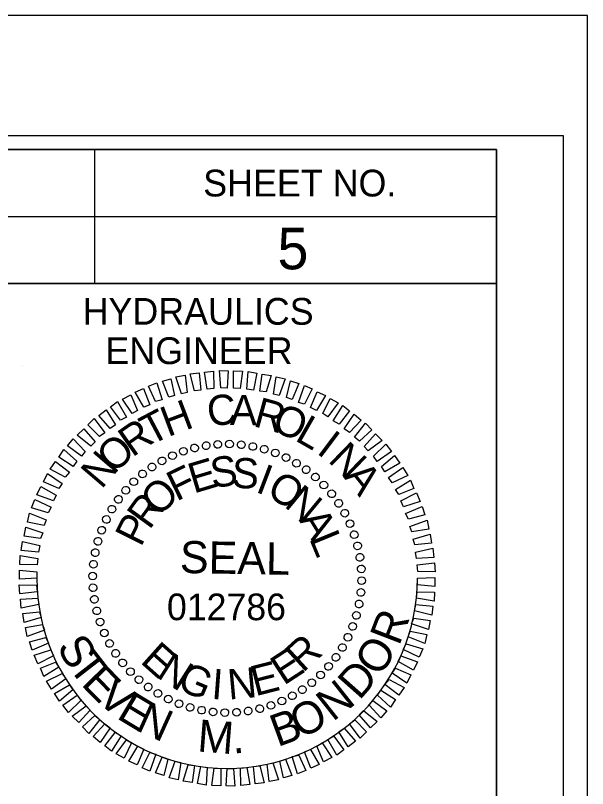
# Model space of a CAD drawing. Extents: x 10033 to 11717, y 9950 to 11050.
# Drawn here: x 11610.3 to 11717, y 10905.6 to 11050 of the extents above; entities that cross this region are included whole.
import ezdxf

# ---------------------------------------------------------------- set-up
doc = ezdxf.new("R2010")
doc.units = 0
for name, color, linetype in [('Default', 7, 'Continuous'), ('Scratch_Level_0', 7, 'Continuous'), ('Sheet Cutting Line CELL', 7, 'Continuous'), ('Sheet Data Field CELL', 7, 'Continuous'), ('Sheet PE Seal CELL', 7, 'Continuous'), ('Sheet Plot Border Inside CELL', 7, 'Continuous'), ('Sheet Plot Border Outside CELL', 7, 'Continuous'), ('Sheet Profile CELL', 7, 'Continuous')]:
    doc.layers.add(name, color=color, linetype=linetype)

msp = doc.modelspace()

# ---------------------------------------------------------------- linework, layer by layer
at = {"layer": 'Scratch_Level_0'}
msp.add_arc((11649.77, 10944.9), 35.5, 180, 360, dxfattribs=at)
at = {"layer": 'Sheet Cutting Line CELL'}
msp.add_line((11717, 11050), (10033, 11050), dxfattribs=at)
at = {"layer": 'Sheet PE Seal CELL'}
for p, q in [((11611.67, 10984.6), (11611.67, 10984.6)), ((11645.87, 10969.65), (11645.87, 10969.65)), ((11648.02, 10969.95), (11648.02, 10969.95)), ((11650.22, 10970), (11650.22, 10970)), ((11652.42, 10969.85), (11652.42, 10969.85)), ((11654.57, 10969.5), (11654.57, 10969.5)), ((11641.57, 10968.65), (11641.57, 10968.65)), ((11643.67, 10969.25), (11643.67, 10969.25)), ((11656.67, 10969.05), (11656.67, 10969.05)), ((11658.77, 10968.35), (11658.77, 10968.35)), ((11637.62, 10966.85), (11637.62, 10966.85)), ((11639.57, 10967.85), (11639.57, 10967.85)), ((11660.77, 10967.45), (11660.77, 10967.45)), ((11635.72, 10965.7), (11635.72, 10965.7)), ((11662.72, 10966.45), (11662.72, 10966.45)), ((11664.52, 10965.2), (11664.52, 10965.2)), ((11633.97, 10964.45), (11633.97, 10964.45)), ((11666.27, 10963.85), (11666.27, 10963.85)), ((11632.32, 10962.95), (11632.32, 10962.95)), ((11667.82, 10962.35), (11667.82, 10962.35)), ((11630.82, 10961.4), (11630.82, 10961.4)), ((11629.47, 10959.65), (11629.47, 10959.65)), ((11669.32, 10960.7), (11669.32, 10960.7)), ((11670.57, 10958.95), (11670.57, 10958.95)), ((11628.22, 10957.85), (11628.22, 10957.85)), ((11671.72, 10957.05), (11671.72, 10957.05)), ((11627.22, 10955.9), (11627.22, 10955.9)), ((11672.72, 10955.1), (11672.72, 10955.1)), ((11626.32, 10953.9), (11626.32, 10953.9)), ((11673.52, 10953.1), (11673.52, 10953.1)), ((11625.62, 10951.8), (11625.62, 10951.8)), ((11674.12, 10951), (11674.12, 10951)), ((11625.17, 10949.7), (11625.17, 10949.7)), ((11674.52, 10948.8), (11674.52, 10948.8)), ((11624.82, 10947.55), (11624.82, 10947.55)), ((11674.82, 10946.65), (11674.82, 10946.65)), ((11624.67, 10945.35), (11624.67, 10945.35)), ((11649.77, 10944.9), (11649.77, 10944.9)), ((11674.87, 10944.45), (11674.87, 10944.45)), ((11624.72, 10943.15), (11624.72, 10943.15)), ((11674.72, 10942.25), (11674.72, 10942.25)), ((11625.02, 10941), (11625.02, 10941)), ((11674.37, 10940.1), (11674.37, 10940.1)), ((11625.42, 10938.8), (11625.42, 10938.8)), ((11673.92, 10938), (11673.92, 10938)), ((11626.02, 10936.7), (11626.02, 10936.7)), ((11673.22, 10935.9), (11673.22, 10935.9)), ((11626.82, 10934.7), (11626.82, 10934.7)), ((11672.32, 10933.9), (11672.32, 10933.9)), ((11627.82, 10932.75), (11627.82, 10932.75)), ((11628.97, 10930.85), (11628.97, 10930.85)), ((11671.32, 10931.95), (11671.32, 10931.95)), ((11630.22, 10929.1), (11630.22, 10929.1)), ((11670.07, 10930.15), (11670.07, 10930.15)), ((11668.72, 10928.4), (11668.72, 10928.4)), ((11631.72, 10927.45), (11631.72, 10927.45)), ((11667.22, 10926.85), (11667.22, 10926.85)), ((11633.27, 10925.95), (11633.27, 10925.95)), ((11665.57, 10925.35), (11665.57, 10925.35)), ((11635.02, 10924.6), (11635.02, 10924.6)), ((11636.82, 10923.35), (11636.82, 10923.35)), ((11663.82, 10924.1), (11663.82, 10924.1)), ((11638.77, 10922.35), (11638.77, 10922.35)), ((11659.97, 10921.95), (11659.97, 10921.95)), ((11661.92, 10922.95), (11661.92, 10922.95)), ((11640.77, 10921.45), (11640.77, 10921.45)), ((11642.87, 10920.75), (11642.87, 10920.75)), ((11655.87, 10920.55), (11655.87, 10920.55)), ((11657.97, 10921.15), (11657.97, 10921.15)), ((11644.97, 10920.3), (11644.97, 10920.3)), ((11647.12, 10919.95), (11647.12, 10919.95)), ((11649.32, 10919.8), (11649.32, 10919.8)), ((11651.52, 10919.85), (11651.52, 10919.85)), ((11653.67, 10920.15), (11653.67, 10920.15))]:
    msp.add_line(p, q, dxfattribs=at)
for points in [[(11641.27, 10979.35), (11640.22, 10982.5), (11641.92, 10982.85), (11642.32, 10979.6)], [(11643.67, 10979.9), (11642.87, 10983.1), (11644.52, 10983.25), (11644.87, 10980.05)], [(11646.07, 10980.2), (11645.52, 10983.4), (11647.22, 10983.6), (11647.27, 10980.35)], [(11648.57, 10980.45), (11648.32, 10983.7), (11649.97, 10983.65), (11649.77, 10980.4)], [(11650.97, 10980.4), (11650.97, 10983.65), (11652.62, 10983.6), (11652.17, 10980.35)], [(11653.47, 10980.25), (11653.67, 10983.5), (11655.32, 10983.2), (11654.67, 10980.05)], [(11655.87, 10979.85), (11656.32, 10983.05), (11657.97, 10982.8), (11657.07, 10979.7)], [(11658.42, 10979.3), (11658.92, 10982.55), (11660.62, 10982.15), (11659.47, 10979.05)], [(11636.42, 10977.9), (11635.12, 10980.8), (11636.62, 10981.4), (11637.67, 10978.2)], [(11638.87, 10978.7), (11637.72, 10981.7), (11639.27, 10982.15), (11639.92, 10979.05)], [(11660.82, 10978.65), (11661.57, 10981.75), (11663.12, 10981.25), (11661.87, 10978.3)], [(11634.22, 10976.85), (11632.62, 10979.65), (11634.17, 10980.35), (11635.32, 10977.3)], [(11663.07, 10977.75), (11664.22, 10980.9), (11665.62, 10980.3), (11664.22, 10977.4)], [(11665.32, 10976.8), (11666.57, 10979.75), (11668.12, 10979.05), (11666.42, 10976.25)], [(11632.07, 10975.65), (11630.22, 10978.35), (11631.77, 10979.15), (11633.02, 10976.25)], [(11667.62, 10975.65), (11668.97, 10978.5), (11670.47, 10977.65), (11668.57, 10975.05)], [(11629.87, 10974.4), (11628.02, 10976.95), (11629.32, 10977.9), (11630.97, 10975)], [(11669.57, 10974.3), (11671.32, 10977.2), (11672.62, 10976.15), (11670.67, 10973.7)], [(11627.97, 10972.9), (11625.82, 10975.3), (11627.17, 10976.35), (11628.92, 10973.55)], [(11671.62, 10972.8), (11673.47, 10975.55), (11674.77, 10974.45), (11672.57, 10972.1)], [(11625.97, 10971.35), (11623.77, 10973.55), (11624.97, 10974.75), (11626.92, 10972.05)], [(11673.52, 10971.25), (11675.57, 10973.85), (11676.77, 10972.65), (11674.47, 10970.5)], [(11624.32, 10969.6), (11621.77, 10971.65), (11623.02, 10972.8), (11625.12, 10970.4)], [(11622.57, 10967.7), (11619.97, 10969.65), (11621.07, 10970.95), (11623.27, 10968.6)], [(11675.32, 10969.5), (11677.47, 10971.85), (11678.67, 10970.65), (11676.07, 10968.7)], [(11677.07, 10967.7), (11679.37, 10969.95), (11680.42, 10968.6), (11677.77, 10966.7)], [(11621.07, 10965.8), (11618.37, 10967.5), (11619.32, 10968.95), (11621.72, 10966.75)], [(11619.57, 10963.8), (11616.77, 10965.3), (11617.77, 10966.7), (11620.37, 10964.7)], [(11678.57, 10965.75), (11681.02, 10967.85), (11681.97, 10966.4), (11679.17, 10964.8)], [(11679.87, 10963.7), (11682.52, 10965.6), (11683.47, 10964.1), (11680.57, 10962.7)], [(11618.37, 10961.65), (11615.52, 10962.9), (11616.27, 10964.45), (11618.97, 10962.6)], [(11681.17, 10961.5), (11683.97, 10963.25), (11684.62, 10961.7), (11681.77, 10960.55)], [(11617.37, 10959.35), (11614.27, 10960.5), (11615.02, 10962.05), (11617.87, 10960.45)], [(11682.17, 10959.35), (11685.12, 10960.85), (11685.77, 10959.25), (11682.67, 10958.25)], [(11616.37, 10957.15), (11613.27, 10958.05), (11613.92, 10959.6), (11616.92, 10958.2)], [(11683.07, 10957), (11686.12, 10958.3), (11686.67, 10956.75), (11683.57, 10955.95)], [(11615.62, 10954.75), (11612.52, 10955.4), (11612.87, 10957.05), (11616.02, 10955.8)], [(11683.87, 10954.6), (11687.07, 10955.75), (11687.37, 10954.1), (11684.22, 10953.55)], [(11614.97, 10952.35), (11611.87, 10952.75), (11612.22, 10954.45), (11615.37, 10953.4)], [(11684.47, 10952.2), (11687.62, 10953.15), (11687.92, 10951.45), (11684.77, 10951.15)], [(11614.57, 10949.8), (11611.37, 10950.1), (11611.57, 10951.8), (11614.82, 10951)], [(11684.92, 10949.8), (11688.17, 10950.5), (11688.32, 10948.8), (11685.12, 10948.6)], [(11614.32, 10947.4), (11611.07, 10947.5), (11611.17, 10949.15), (11614.42, 10948.6)], [(11614.27, 10944.9), (11611.02, 10944.75), (11611.02, 10946.45), (11614.27, 10946.1)], [(11685.22, 10947.4), (11688.47, 10947.8), (11688.57, 10946.1), (11685.32, 10946.2)], [(11685.27, 10944.9), (11688.52, 10945.05), (11688.52, 10943.35), (11685.27, 10943.7)], [(11614.32, 10942.4), (11611.07, 10942), (11610.97, 10943.7), (11614.22, 10943.6)], [(11685.22, 10942.4), (11688.47, 10942.3), (11688.37, 10940.65), (11685.12, 10941.2)], [(11614.62, 10940), (11611.37, 10939.3), (11611.22, 10941), (11614.42, 10941.2)], [(11684.97, 10940), (11688.17, 10939.7), (11687.97, 10938), (11684.72, 10938.8)], [(11615.07, 10937.6), (11611.92, 10936.65), (11611.62, 10938.35), (11614.77, 10938.65)], [(11684.57, 10937.45), (11687.67, 10937.05), (11687.32, 10935.35), (11684.17, 10936.4)], [(11615.67, 10935.2), (11612.47, 10934.05), (11612.17, 10935.7), (11615.32, 10936.25)], [(11683.92, 10935.05), (11687.02, 10934.4), (11686.67, 10932.75), (11683.52, 10934)], [(11616.47, 10932.8), (11613.42, 10931.5), (11612.87, 10933.05), (11615.97, 10933.85)], [(11683.17, 10932.65), (11686.27, 10931.75), (11685.62, 10930.2), (11682.62, 10931.6)], [(11617.37, 10930.45), (11614.42, 10928.95), (11613.77, 10930.55), (11616.87, 10931.55)], [(11618.37, 10928.3), (11615.57, 10926.55), (11614.92, 10928.1), (11617.77, 10929.25)], [(11682.17, 10930.45), (11685.27, 10929.3), (11684.52, 10927.75), (11681.67, 10929.35)], [(11681.17, 10928.15), (11684.02, 10926.9), (11683.27, 10925.35), (11680.57, 10927.2)], [(11619.67, 10926.1), (11617.02, 10924.2), (11616.07, 10925.7), (11618.97, 10927.1)], [(11620.97, 10924.05), (11618.52, 10921.95), (11617.57, 10923.4), (11620.37, 10925)], [(11679.97, 10926), (11682.77, 10924.5), (11681.77, 10923.1), (11679.17, 10925.1)], [(11678.47, 10924), (11681.17, 10922.3), (11680.22, 10920.85), (11677.82, 10923.05)], [(11622.47, 10922.1), (11620.17, 10919.85), (11619.12, 10921.2), (11621.77, 10923.1)], [(11676.97, 10922.1), (11679.57, 10920.15), (11678.47, 10918.85), (11676.27, 10921.2)], [(11624.22, 10920.3), (11622.07, 10917.95), (11620.87, 10919.15), (11623.47, 10921.1)], [(11626.02, 10918.55), (11623.97, 10915.95), (11622.77, 10917.15), (11625.07, 10919.3)], [(11675.22, 10920.2), (11677.77, 10918.15), (11676.52, 10917), (11674.42, 10919.4)], [(11627.92, 10917), (11626.07, 10914.25), (11624.77, 10915.35), (11626.97, 10917.7)], [(11673.57, 10918.45), (11675.77, 10916.25), (11674.57, 10915.05), (11672.62, 10917.75)], [(11629.97, 10915.5), (11628.22, 10912.6), (11626.92, 10913.65), (11628.87, 10916.1)], [(11671.57, 10916.9), (11673.72, 10914.5), (11672.37, 10913.45), (11670.62, 10916.25)], [(11631.92, 10914.15), (11630.57, 10911.3), (11629.07, 10912.15), (11630.97, 10914.75)], [(11669.67, 10915.4), (11671.52, 10912.85), (11670.22, 10911.9), (11668.57, 10914.8)], [(11634.22, 10913), (11632.97, 10910.05), (11631.42, 10910.75), (11633.12, 10913.55)], [(11667.47, 10914.15), (11669.32, 10911.45), (11667.77, 10910.65), (11666.52, 10913.55)], [(11636.47, 10912.05), (11635.32, 10908.9), (11633.92, 10909.5), (11635.32, 10912.4)], [(11663.12, 10911.9), (11664.42, 10909), (11662.92, 10908.4), (11661.87, 10911.6)], [(11665.32, 10912.95), (11666.92, 10910.15), (11665.37, 10909.45), (11664.22, 10912.5)], [(11638.72, 10911.15), (11637.97, 10908.05), (11636.42, 10908.55), (11637.67, 10911.5)], [(11641.12, 10910.5), (11640.62, 10907.25), (11638.92, 10907.65), (11640.07, 10910.75)], [(11658.27, 10910.45), (11659.32, 10907.3), (11657.62, 10906.95), (11657.22, 10910.2)], [(11660.67, 10911.1), (11661.82, 10908.1), (11660.27, 10907.65), (11659.62, 10910.75)], [(11643.67, 10909.95), (11643.22, 10906.75), (11641.57, 10907), (11642.47, 10910.1)], [(11646.07, 10909.55), (11645.87, 10906.3), (11644.22, 10906.6), (11644.87, 10909.75)], [(11648.57, 10909.4), (11648.57, 10906.15), (11646.92, 10906.2), (11647.37, 10909.45)], [(11650.97, 10909.35), (11651.22, 10906.1), (11649.57, 10906.15), (11649.77, 10909.4)], [(11653.47, 10909.6), (11654.02, 10906.4), (11652.32, 10906.2), (11652.27, 10909.45)], [(11655.87, 10909.9), (11656.67, 10906.7), (11655.02, 10906.55), (11654.67, 10909.75)]]:
    msp.add_lwpolyline(points, close=True, dxfattribs=at)
for centre, major_axis in [((11643.7, 10969.23), (-0.174, 0.699)), ((11645.85, 10969.67), (-0.113, 0.711)), ((11648.02, 10969.91), (-0.05, 0.718)), ((11650.21, 10969.97), (0.013, 0.72)), ((11652.39, 10969.84), (0.075, 0.716)), ((11654.56, 10969.51), (0.137, 0.707)), ((11656.68, 10969), (0.198, 0.692)), ((11639.57, 10967.81), (-0.293, 0.658)), ((11641.61, 10968.61), (-0.234, 0.681)), ((11658.76, 10968.31), (0.258, 0.672)), ((11660.77, 10967.44), (0.316, 0.647)), ((11637.61, 10966.83), (-0.349, 0.63)), ((11662.69, 10966.39), (0.371, 0.617)), ((11633.99, 10964.39), (-0.453, 0.56)), ((11635.75, 10965.69), (-0.403, 0.597)), ((11664.51, 10965.19), (0.423, 0.582)), ((11632.35, 10962.94), (-0.5, 0.518)), ((11666.23, 10963.82), (0.472, 0.543)), ((11667.81, 10962.32), (0.518, 0.5)), ((11630.84, 10961.35), (-0.543, 0.472)), ((11669.26, 10960.68), (0.56, 0.453)), ((11629.48, 10959.64), (-0.582, 0.423)), ((11670.56, 10958.92), (0.597, 0.403)), ((11628.27, 10957.81), (-0.617, 0.371)), ((11627.23, 10955.89), (-0.647, 0.316)), ((11671.71, 10957.05), (0.63, 0.349)), ((11672.68, 10955.1), (0.658, 0.293)), ((11626.36, 10953.88), (-0.672, 0.258)), ((11673.48, 10953.06), (0.681, 0.234)), ((11625.66, 10951.81), (-0.692, 0.198)), ((11674.11, 10950.96), (0.699, 0.174)), ((11625.15, 10949.68), (-0.707, 0.137)), ((11674.54, 10948.82), (0.711, 0.113)), ((11624.83, 10947.52), (-0.716, 0.075)), ((11674.79, 10946.65), (0.718, 0.05)), ((11624.69, 10945.33), (-0.72, 0.013)), ((11674.85, 10944.46), (0.72, -0.013)), ((11624.75, 10943.15), (-0.718, -0.05)), ((11674.71, 10942.27), (0.716, -0.075)), ((11625, 10940.97), (-0.711, -0.113)), ((11674.39, 10940.11), (0.707, -0.137)), ((11625.44, 10938.83), (-0.699, -0.174)), ((11673.88, 10937.98), (0.692, -0.198)), ((11626.06, 10936.73), (-0.681, -0.234)), ((11673.19, 10935.91), (0.672, -0.258)), ((11626.86, 10934.69), (-0.658, -0.293)), ((11627.84, 10932.74), (-0.63, -0.349)), ((11672.31, 10933.9), (0.647, -0.316)), ((11671.27, 10931.98), (0.617, -0.371)), ((11628.98, 10930.87), (-0.597, -0.403)), ((11670.06, 10930.15), (0.582, -0.423)), ((11630.28, 10929.11), (-0.56, -0.453)), ((11668.7, 10928.44), (0.543, -0.472)), ((11631.73, 10927.47), (-0.518, -0.5)), ((11667.19, 10926.85), (0.5, -0.518)), ((11633.32, 10925.97), (-0.472, -0.543)), ((11665.55, 10925.4), (0.453, -0.56)), ((11635.03, 10924.61), (-0.423, -0.582)), ((11663.8, 10924.1), (0.403, -0.597)), ((11636.85, 10923.4), (-0.371, -0.617)), ((11661.93, 10922.96), (0.349, -0.63)), ((11638.78, 10922.35), (-0.316, -0.647)), ((11640.78, 10921.48), (-0.258, -0.672)), ((11657.94, 10921.18), (0.234, -0.681)), ((11659.97, 10921.98), (0.293, -0.658)), ((11642.86, 10920.79), (-0.198, -0.692)), ((11644.99, 10920.28), (-0.137, -0.707)), ((11647.15, 10919.95), (-0.075, -0.716)), ((11649.33, 10919.82), (-0.013, -0.72)), ((11651.52, 10919.88), (0.05, -0.718)), ((11653.69, 10920.12), (0.113, -0.711)), ((11655.84, 10920.56), (0.174, -0.699))]:
    msp.add_ellipse(centre, major_axis=major_axis, ratio=0.999708, dxfattribs=at)
at = {"layer": 'Sheet Plot Border Inside CELL'}
msp.add_lwpolyline([(11712.5, 11027.55), (10046, 11027.55), (10046, 9972.45), (11712.5, 9972.45)], close=True, dxfattribs=at)
at = {"layer": 'Sheet Plot Border Outside CELL'}
msp.add_lwpolyline([(11717, 11050), (10033, 11050), (10033, 9950), (11717, 9950)], close=True, dxfattribs=at)
at = {"layer": 'Sheet Profile CELL'}
for p, q in [((11625, 11024.95), (11625, 10999.95)), ((11499.95, 11012.45), (11700, 11012.45))]:
    msp.add_line(p, q, dxfattribs=at)
for points in [[(11700, 11025), (10200, 11025), (10200, 9975), (11700, 9975)], [(11499.95, 11025), (11700, 11025), (11700, 10999.95), (11499.95, 10999.95)], [(11600, 10999.95), (11700, 10999.95), (11700, 10887.45), (11600, 10887.45)]]:
    msp.add_lwpolyline(points, close=True, dxfattribs=at)

# ---------------------------------------------------------------- texts
at = {"layer": 'Default'}
for s, rotation, p in [('R', 68.9067, (11681.84, 10932.15)), ('S', 300.8985, (11617.86, 10932.07)), ('O', 57.9211, (11678.29, 10926.33)), ('T', 307.86, (11619.99, 10928.31)), ('E', 314.3221, (11622.36, 10925.08)), ('D', 48.5364, (11674.42, 10921.98)), ('V', 321.0779, (11625.22, 10922)), ('N', 38.3439, (11669.48, 10918.03)), ('E', 328.9205, (11628.95, 10918.88)), ('O', 27.3584, (11663.46, 10914.83)), ('N', 335.6763, (11632.49, 10916.63)), ('B', 20.0445, (11659.17, 10913.36)), ('M', 355.562, (11644.1, 10912.58)), ('.', 6.5181, (11650.88, 10912.13))]:
    msp.add_text(s, height=6, rotation=rotation, dxfattribs=at).set_placement(p)
at = {"layer": 'Sheet Data Field CELL'}
msp.add_text('5', height=7.75, dxfattribs=at).set_placement((11659.16, 11002.6))
at = {"layer": 'Sheet PE Seal CELL'}
for s, height, rotation, p in [('H', 5.64, 20.6195, (11638.72, 10971.25)), ('C', 5.64, 6.2199, (11646.32, 10973.25)), ('A', 5.64, 359.0203, (11650.27, 10973.55)), ('R', 5.64, 344.6211, (11654.47, 10973.35)), ('O', 5.64, 337.4212, (11657.82, 10972.6)), ('T', 5.64, 27.8198, (11635.47, 10969.6)), ('L', 5.64, 330.2209, (11662.22, 10970.75)), ('R', 5.64, 35.0205, (11632.07, 10967.4)), ('I', 5.64, 323.0201, (11666.27, 10968.35)), ('O', 5.64, 42.2217, (11628.62, 10964.3)), ('N', 5.64, 315.8189, (11668.42, 10966.8)), ('N', 5.64, 49.4235, (11626.32, 10961.4)), ('E', 5.64, 16.6111, (11643.52, 10960.7)), ('S', 5.64, 7.2556, (11646.97, 10961.75)), ('S', 5.64, 357.9004, (11650.57, 10961.8)), ('F', 5.64, 25.967, (11640.32, 10959.2)), ('I', 5.64, 339.1896, (11654.87, 10961.1)), ('A', 5.64, 308.6172, (11671.37, 10963.85)), ('O', 5.64, 329.8335, (11656.87, 10960.4)), ('O', 5.64, 44.6812, (11637.02, 10956.25)), ('N', 5.64, 320.4766, (11660.22, 10958.4)), ('R', 5.64, 54.0397, (11635.27, 10953.8)), ('P', 5.64, 63.3989, (11633.67, 10950.6)), ('A', 5.64, 301.7603, (11663.07, 10955.8)), ('L', 5.64, 292.4008, (11665.02, 10952.35)), ('SEAL', 5.998, 359, (11640.92, 10945.9)), ('R', 5.64, 42.4814, (11663.87, 10927.15)), ('E', 5.64, 318.2769, (11633.37, 10929.25)), ('E', 5.64, 33.1241, (11660.32, 10924.8)), ('N', 5.64, 327.634, (11636.37, 10926.55)), ('E', 5.64, 14.4118, (11655.02, 10922.85)), ('G', 5.64, 336.9902, (11640.17, 10924.3)), ('I', 5.64, 355.7012, (11646.72, 10922.4)), ('N', 5.64, 5.0564, (11650.07, 10922.25))]:
    msp.add_text(s, height=height, rotation=rotation, dxfattribs=at).set_placement(p)
msp.add_text('012786', height=4.975, dxfattribs=at).set_placement((11638.54, 10937.08))
at = {"layer": 'Sheet Profile CELL'}
for s, p in [('SHEET NO.', (11645.3, 11016.2)), ('HYDRAULICS', (11622.8, 10992.25)), ('ENGINEER', (11627.05, 10984.9))]:
    msp.add_text(s, height=5, dxfattribs=at).set_placement(p)

doc.saveas('drawing.dxf')
